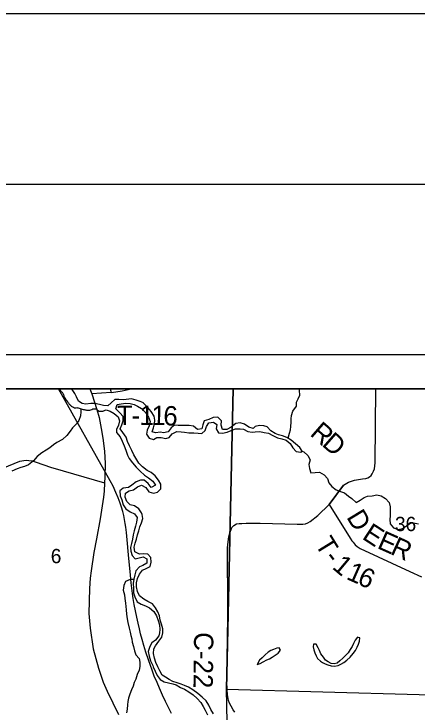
# Model space of a CAD drawing. Extents: x 0 to 34, y 0 to 22.
# Drawn here: x 3.131 to 4.316, y 19.951 to 22 of the extents above; entities that cross this region are included whole.
import ezdxf

# ---------------------------------------------------------------- set-up
doc = ezdxf.new("R2010")
doc.units = 0
for name, color, linetype in [('Default', 7, 'Continuous'), ('GM_X_Corporation', 7, 'Continuous'), ('GM_X_County_Road', 7, 'Continuous'), ('GM_X_County_Road_Text', 7, 'Continuous'), ('GM_X_Interchange_Ramps', 7, 'Continuous'), ('GM_X_Interstate_Route', 7, 'Continuous'), ('GM_X_Major_Lake', 7, 'Continuous'), ('GM_X_Minor_Lake', 7, 'Continuous'), ('GM_X_Minor_River', 7, 'Continuous'), ('GM_X_Section', 7, 'Continuous'), ('GM_X_Township_Road_Text', 7, 'Continuous'), ('GM_X_US_Location', 7, 'Continuous'), ('SH_Border', 7, 'Continuous'), ('SH_Cut_Line', 7, 'Continuous'), ('SH_Data', 7, 'Continuous')]:
    doc.layers.add(name, color=color, linetype=linetype)

msp = doc.modelspace()

# ---------------------------------------------------------------- linework, layer by layer
at = {"layer": 'Default'}
for points in [[(3.7753, 20.9), (2.759, 20.9), (2.7373, 19.9264), (3.7574, 19.9211), (3.7556, 20.0185)], [(4.6239, 20.9), (3.7753, 20.9), (3.7556, 20.0185), (4.6053, 19.9945)]]:
    msp.add_lwpolyline(points, close=True, dxfattribs=at)
at = {"layer": 'GM_X_Corporation'}
for p, q in [((3.4141, 20.9), (3.4158, 20.8932)), ((4.0581, 20.5598), (4.1002, 20.6166))]:
    msp.add_line(p, q, dxfattribs=at)
for points in [[(3.4158, 20.8932), (3.4167, 20.8893), (3.3604, 20.8845)], [(4.1002, 20.6166), (4.1043, 20.6195), (4.1095, 20.6228), (4.1148, 20.6254), (4.1206, 20.6281), (4.132, 20.6311), (4.1561, 20.6354), (4.1654, 20.6364), (4.1718, 20.6385), (4.1765, 20.6414), (4.1811, 20.6457), (4.1844, 20.6506), (4.1879, 20.6576), (4.1908, 20.6646), (4.1925, 20.682), (4.1951, 20.9)], [(3.7801, 19.9505), (3.7759, 19.9571), (3.7694, 19.9679), (3.7648, 19.9768), (3.7621, 19.9844), (3.7606, 19.9905), (3.7584, 20.0025), (3.7574, 20.0156), (3.7573, 20.0422), (3.7594, 20.2318), (3.7596, 20.3052), (3.7592, 20.384), (3.7584, 20.4326), (3.7603, 20.4504), (3.7625, 20.4648), (3.7655, 20.4764), (3.7714, 20.493), (3.7771, 20.4984), (3.7855, 20.5033), (3.7931, 20.5046), (3.8005, 20.5047), (3.8132, 20.505), (3.8548, 20.5052), (3.9639, 20.5027), (3.973, 20.5027), (3.9807, 20.5023), (3.988, 20.5034), (3.9948, 20.506), (4.0019, 20.5104), (4.0241, 20.5275), (4.0581, 20.5598)]]:
    msp.add_lwpolyline(points, dxfattribs=at)
at = {"layer": 'GM_X_County_Road'}
msp.add_lwpolyline([(3.5943, 19.9464), (3.584, 19.9663), (3.5763, 19.9823), (3.5674, 20.0008), (3.5587, 20.021), (3.5518, 20.0372), (3.5437, 20.0566), (3.5373, 20.0738), (3.5322, 20.0878), (3.5262, 20.1046), (3.519, 20.1265), (3.513, 20.1461), (3.5081, 20.1639), (3.5035, 20.1807), (3.5001, 20.1947), (3.4961, 20.2113), (3.4921, 20.2296), (3.4885, 20.2476), (3.4849, 20.2668), (3.4817, 20.284), (3.4796, 20.2991), (3.4775, 20.3141), (3.4755, 20.3304), (3.4733, 20.3522), (3.4677, 20.4128), (3.4638, 20.4563), (3.4618, 20.4781), (3.46, 20.4932), (3.4583, 20.5039), (3.4564, 20.5158), (3.4536, 20.5281), (3.4509, 20.5397), (3.4473, 20.552), (3.4434, 20.5644), (3.4377, 20.5792), (3.431, 20.5955), (3.4223, 20.6138), (3.4135, 20.63), (3.2617, 20.9)], dxfattribs=at)
at = {"layer": 'GM_X_Interchange_Ramps'}
msp.add_lwpolyline([(6.6698, 20.9), (2.1, 20.9), (2.1, 17.9098), (2.4376, 17.9025), (2.6711, 17.8975), (2.9484, 17.8857), (3.604, 17.8577), (3.7063, 17.8588), (3.7128, 17.9822), (4.1825, 17.9744), (4.4481, 17.9728), (4.5919, 17.9719), (4.9267, 17.9702), (4.9368, 17.9702), (4.994, 17.969), (5.3871, 17.9608), (5.6339, 17.9555), (6.0729, 17.9463), (6.24, 17.9427), (6.5943, 17.9356), (6.6079, 18.3189), (6.6258, 18.9603), (6.6304, 19.2166), (6.6438, 19.9593)], close=True, dxfattribs=at)
msp.add_lwpolyline([(3.3543, 20.9), (3.3604, 20.8845), (3.3747, 20.8388), (3.3814, 20.8155), (3.3876, 20.7833), (3.3926, 20.7546), (3.397, 20.7163), (3.3991, 20.6806), (3.3987, 20.6401), (3.3974, 20.624), (3.3964, 20.5991), (3.3941, 20.5816), (3.3843, 20.5177), (3.3737, 20.4598), (3.3662, 20.4188), (3.3585, 20.365), (3.3553, 20.3435), (3.3529, 20.3131), (3.3508, 20.2405), (3.3556, 20.1975), (3.3642, 20.1369), (3.3796, 20.0796), (3.3936, 20.0384), (3.4051, 20.0126), (3.4382, 19.944)], dxfattribs=at)
at = {"layer": 'GM_X_Interstate_Route'}
msp.add_line((4.1002, 20.6166), (4.0581, 20.5598), dxfattribs=at)
for points in [[(3.4167, 20.8893), (3.4309, 20.8907), (3.4489, 20.8938), (3.4761, 20.9)], [(3.0356, 20.6412), (3.1485, 20.6871), (3.1599, 20.6897), (3.1671, 20.6903), (3.1749, 20.6897), (3.1845, 20.6879), (3.1961, 20.6843), (3.2381, 20.6695), (3.2761, 20.6591), (3.3974, 20.624)], [(4.0581, 20.5598), (4.1198, 20.461), (4.1245, 20.4536), (4.1282, 20.4492), (4.134, 20.4419), (4.1396, 20.4373), (4.1491, 20.4311), (4.2946, 20.3639), (4.3294, 20.3474)]]:
    msp.add_lwpolyline(points, dxfattribs=at)
at = {"layer": 'GM_X_Minor_Lake'}
msp.add_lwpolyline([(3.7556, 20.0185), (4.6053, 19.9945), (4.5812, 18.9996), (3.7421, 19.0151), (3.7574, 19.9211)], close=True, dxfattribs=at)
at = {"layer": 'GM_X_Minor_River'}
for points in [[(4.0193, 20.1503), (4.0114, 20.1506), (4.0107, 20.1419), (4.013, 20.1336), (4.0154, 20.1249), (4.0193, 20.1158), (4.0231, 20.1083), (4.0319, 20.1), (4.0377, 20.0966), (4.046, 20.0929), (4.0541, 20.0892), (4.0632, 20.0862), (4.0735, 20.0855), (4.0837, 20.0879), (4.0916, 20.091), (4.1007, 20.0968), (4.1094, 20.1033), (4.1192, 20.1121), (4.1282, 20.1224), (4.135, 20.132), (4.1402, 20.1415), (4.1439, 20.1503), (4.1465, 20.1594), (4.1476, 20.1685), (4.1433, 20.1701)], [(4.1433, 20.1701), (4.1407, 20.1711), (4.1336, 20.1619), (4.1291, 20.152), (4.125, 20.1433), (4.1198, 20.1341), (4.1134, 20.125), (4.1059, 20.1169), (4.0976, 20.1089), (4.0889, 20.1008), (4.081, 20.0947), (4.0726, 20.0924), (4.0639, 20.0934), (4.0551, 20.0983), (4.0471, 20.1035), (4.0406, 20.1122), (4.0329, 20.122), (4.029, 20.1311), (4.0255, 20.1398), (4.0193, 20.1503)], [(3.912, 20.1376), (3.9112, 20.1392), (3.9036, 20.1387), (3.8945, 20.1345), (3.8866, 20.1314), (3.8783, 20.1264), (3.87, 20.1187), (3.8605, 20.1099), (3.853, 20.1034), (3.8463, 20.0908)], [(3.8463, 20.0908), (3.855, 20.0935), (3.8641, 20.0978), (3.8743, 20.104), (3.8818, 20.1074), (3.8901, 20.1124), (3.8985, 20.1178), (3.9075, 20.1236), (3.9147, 20.1328), (3.912, 20.1376)]]:
    msp.add_lwpolyline(points, dxfattribs=at)
at = {"layer": 'GM_X_Township_Road_Text'}
for points in [[(3.937, 20.7548), (3.9406, 20.7692), (3.9443, 20.7791), (3.9453, 20.7886), (3.9464, 20.8015), (3.9459, 20.8114), (3.9473, 20.8216), (3.951, 20.8338), (3.9615, 20.8487), (3.9618, 20.8601), (3.9663, 20.8707), (3.9711, 20.8814), (3.9706, 20.8947), (3.9696, 20.9)], [(3.3279, 20.8414), (3.3281, 20.8318), (3.3267, 20.8208), (3.3215, 20.8067), (3.3147, 20.7968), (3.3031, 20.7853), (3.2967, 20.7758), (3.2869, 20.7628), (3.2734, 20.7513), (3.2575, 20.7421), (3.2477, 20.7348), (3.2367, 20.7263), (3.2262, 20.7198), (3.2133, 20.7113), (3.1994, 20.7006), (3.1881, 20.688), (3.1737, 20.6765), (3.1624, 20.6714), (3.1518, 20.6687), (3.1404, 20.6652), (3.1253, 20.6582)], [(3.4835, 20.3401), (3.4726, 20.3395), (3.4594, 20.3337), (3.4542, 20.3219), (3.4524, 20.3086), (3.4559, 20.2954), (3.4575, 20.2844), (3.4588, 20.2707), (3.4605, 20.251), (3.4621, 20.2385), (3.4638, 20.2241), (3.4661, 20.2135), (3.4693, 20.1972), (3.4725, 20.1855), (3.4748, 20.1753), (3.4772, 20.1654), (3.4788, 20.1556), (3.4823, 20.1431), (3.4859, 20.1302), (3.4894, 20.1185), (3.499, 20.1076), (3.501, 20.097), (3.5007, 20.0844), (3.4989, 20.0734), (3.4937, 20.0612), (3.4889, 20.0475), (3.4848, 20.038), (3.4811, 20.0266), (3.4766, 20.0163), (3.4718, 20.0038), (3.4681, 19.9916), (3.4663, 19.9817), (3.4652, 19.9722), (3.4642, 19.9597), (3.462, 19.9483)]]:
    msp.add_lwpolyline(points, dxfattribs=at)
at = {"layer": 'GM_X_US_Location'}
for points in [[(3.4067, 20.85), (3.3945, 20.8509), (3.3823, 20.8541), (3.369, 20.8565), (3.3568, 20.8567), (3.3424, 20.855), (3.3321, 20.8563), (3.3206, 20.8633), (3.3147, 20.8765), (3.3099, 20.8863), (3.3018, 20.8975), (3.2992, 20.9)], [(3.5119, 20.8582), (3.5023, 20.8622), (3.4901, 20.8661), (3.4771, 20.8705), (3.4528, 20.867), (3.4395, 20.8683), (3.4281, 20.8681), (3.4172, 20.8581), (3.4067, 20.85)], [(3.5063, 20.5356), (3.4981, 20.5476), (3.4858, 20.5558), (3.4728, 20.5594), (3.4628, 20.5687), (3.4584, 20.5815), (3.4593, 20.5936), (3.4702, 20.6003), (3.4823, 20.6028), (3.4947, 20.6124), (3.5064, 20.6164), (3.5191, 20.6098), (3.528, 20.5974), (3.541, 20.5935), (3.5531, 20.5967), (3.5625, 20.6064), (3.563, 20.62), (3.5564, 20.6317), (3.5459, 20.6444), (3.5347, 20.6541), (3.5224, 20.6599), (3.5093, 20.6707), (3.4985, 20.6819), (3.4895, 20.6962), (3.4836, 20.7063), (3.4773, 20.7191), (3.4707, 20.7327), (3.4647, 20.7455), (3.4611, 20.7576), (3.4514, 20.7714), (3.4436, 20.7823), (3.448, 20.7937), (3.4519, 20.806), (3.4521, 20.8189), (3.442, 20.8293), (3.4304, 20.8413), (3.4348, 20.8538), (3.4465, 20.8559), (3.4602, 20.8577), (3.4728, 20.8564), (3.4842, 20.8539), (3.4938, 20.8491), (3.5064, 20.8421), (3.5177, 20.8306), (3.527, 20.8167), (3.5314, 20.8035), (3.5286, 20.7913), (3.5223, 20.7787), (3.5206, 20.7661), (3.5281, 20.7545), (3.541, 20.7509), (3.5512, 20.7564), (3.5641, 20.757), (3.5779, 20.7542), (3.5877, 20.757), (3.5959, 20.7678), (3.6102, 20.7748), (3.6224, 20.7731), (3.6323, 20.7725), (3.6453, 20.7709), (3.6601, 20.77), (3.673, 20.7694), (3.6829, 20.7681), (3.6934, 20.777), (3.6966, 20.7888), (3.7044, 20.8003), (3.7173, 20.8017), (3.7277, 20.7946), (3.7256, 20.7824), (3.7319, 20.7708), (3.7441, 20.7691), (3.7574, 20.7724), (3.7694, 20.7771), (3.7827, 20.7823), (3.7956, 20.7825), (3.8059, 20.7808), (3.8182, 20.7741), (3.8311, 20.7721), (3.8406, 20.7737), (3.8543, 20.774), (3.8669, 20.7711), (3.8798, 20.7698), (3.8925, 20.7628), (3.9059, 20.7562), (3.9181, 20.7527), (3.9315, 20.7487), (3.9434, 20.739), (3.9505, 20.7266), (3.9609, 20.7158), (3.9739, 20.7137), (3.9784, 20.7165)], [(3.8343, 20.7835), (3.8217, 20.7875), (3.809, 20.7964), (3.7957, 20.7999), (3.7832, 20.7978), (3.7693, 20.7873), (3.7565, 20.7803), (3.7439, 20.7801), (3.7403, 20.7926), (3.7416, 20.8059), (3.73, 20.8163), (3.7164, 20.8153), (3.7043, 20.8098), (3.6907, 20.8061), (3.6867, 20.7943), (3.6831, 20.7821), (3.6709, 20.7804), (3.659, 20.7897), (3.646, 20.7921), (3.6236, 20.7917), (3.6137, 20.7923), (3.6031, 20.7925), (3.5933, 20.7852), (3.5848, 20.7737), (3.5711, 20.7708), (3.5616, 20.7725), (3.5476, 20.77), (3.5373, 20.7732), (3.5409, 20.7851), (3.5445, 20.7965), (3.5454, 20.8079), (3.5429, 20.8196), (3.5347, 20.8328), (3.5246, 20.8451), (3.5111, 20.8582), (3.5119, 20.8582)], [(3.4021, 20.8376), (3.4138, 20.8341), (3.4253, 20.8275), (3.4373, 20.8178), (3.4413, 20.8058), (3.4381, 20.7932), (3.4322, 20.7806), (3.4328, 20.7711), (3.4429, 20.7584), (3.4495, 20.746), (3.4547, 20.732), (3.4599, 20.7192), (3.4647, 20.7049), (3.4698, 20.6951), (3.4791, 20.682), (3.4903, 20.6693), (3.5023, 20.6581), (3.5147, 20.6458), (3.527, 20.638), (3.5397, 20.6287), (3.5467, 20.6167), (3.5343, 20.6105), (3.5257, 20.6217), (3.5134, 20.6313), (3.5035, 20.6319), (3.4899, 20.6264), (3.4775, 20.6171), (3.4674, 20.6097), (3.4526, 20.6079), (3.4428, 20.6002), (3.4438, 20.5858), (3.4486, 20.5734), (3.4526, 20.5594), (3.4601, 20.5478), (3.4724, 20.5381), (3.4854, 20.5326), (3.4936, 20.5218), (3.4915, 20.5081), (3.4887, 20.4963), (3.4847, 20.4833), (3.4815, 20.4711), (3.4794, 20.4582), (3.477, 20.446), (3.4741, 20.4338), (3.4747, 20.4232), (3.4787, 20.41), (3.4876, 20.4003), (3.4993, 20.4039), (3.5111, 20.4064), (3.5218, 20.4008), (3.522, 20.3883), (3.5104, 20.3809), (3.4998, 20.3773), (3.4897, 20.3658), (3.4869, 20.354), (3.4837, 20.3414), (3.482, 20.3281), (3.4826, 20.3145), (3.4828, 20.3008), (3.4861, 20.2887), (3.4931, 20.2748), (3.5051, 20.2674), (3.5181, 20.2631), (3.5299, 20.2572), (3.5419, 20.2464), (3.5505, 20.2336), (3.5553, 20.2201), (3.5589, 20.2072), (3.5599, 20.1936), (3.5585, 20.1837), (3.5568, 20.1742), (3.5471, 20.1619), (3.5362, 20.1537), (3.5303, 20.143), (3.526, 20.1282), (3.5289, 20.1149), (3.5329, 20.1017), (3.5389, 20.0874)], [(3.9784, 20.7165), (3.971, 20.7274), (3.9583, 20.7378), (3.9459, 20.7493), (3.9332, 20.7571), (3.9202, 20.7614), (3.9088, 20.765), (3.8992, 20.7683), (3.8862, 20.7764), (3.8753, 20.7884), (3.8658, 20.7912), (3.8532, 20.7918), (3.8399, 20.7893), (3.8343, 20.7835)], [(3.9784, 20.7165), (3.983, 20.7143), (3.9946, 20.7038), (4.002, 20.6911), (3.9981, 20.6774), (4.0001, 20.666), (4.0042, 20.6532), (4.0167, 20.6541), (4.0296, 20.6547), (4.0427, 20.6474), (4.0527, 20.6365), (4.0571, 20.6241), (4.0657, 20.6125), (4.0787, 20.6036), (4.091, 20.5985), (4.1032, 20.5941), (4.1144, 20.5848), (4.124, 20.5774), (4.1368, 20.5662), (4.1492, 20.5729), (4.1609, 20.5803), (4.1707, 20.5846), (4.184, 20.5856), (4.198, 20.5881), (4.2106, 20.5857), (4.2232, 20.5775), (4.2345, 20.5663), (4.237, 20.5535), (4.2372, 20.5398), (4.2366, 20.5273), (4.2357, 20.5163), (4.2374, 20.503), (4.2467, 20.4914), (4.2601, 20.4863), (4.2734, 20.4896), (4.2854, 20.4977), (4.2982, 20.5063), (4.3104, 20.505), (4.3199, 20.5032)], [(3.7172, 19.9458), (3.7094, 19.9582), (3.7039, 19.9706), (3.6964, 19.9834), (3.6848, 19.995), (3.6714, 20.0054), (3.6571, 20.0165), (3.6445, 20.0239), (3.6322, 20.029), (3.6226, 20.0323), (3.6104, 20.0362), (3.5978, 20.0406), (3.5878, 20.0465), (3.5763, 20.0535), (3.5667, 20.059), (3.5596, 20.0718), (3.5545, 20.0839), (3.5482, 20.0959), (3.5442, 20.1095), (3.5413, 20.1231), (3.5418, 20.136), (3.5474, 20.1456), (3.5567, 20.1586), (3.566, 20.1705), (3.5684, 20.1831), (3.5686, 20.1953), (3.565, 20.2085), (3.5613, 20.2205), (3.5585, 20.233), (3.5545, 20.2451), (3.5474, 20.2571), (3.5381, 20.2683), (3.5251, 20.2749), (3.5128, 20.282), (3.4997, 20.2916), (3.4942, 20.3048), (3.4917, 20.318), (3.4911, 20.3302), (3.4947, 20.3431), (3.4998, 20.3553), (3.5087, 20.3669), (3.52, 20.3724), (3.5317, 20.3782), (3.5345, 20.3908), (3.5336, 20.4045), (3.5246, 20.4142), (3.5121, 20.4155), (3.4999, 20.4145), (3.4865, 20.4215), (3.4848, 20.4344), (3.4872, 20.4465), (3.4916, 20.458), (3.4944, 20.4706), (3.498, 20.4824), (3.5016, 20.4946), (3.5064, 20.5064), (3.5096, 20.5194), (3.5075, 20.5307), (3.5063, 20.5356)], [(3.5389, 20.0874), (3.5401, 20.0832), (3.5519, 20.0584), (3.5612, 20.046), (3.5731, 20.0394), (3.5849, 20.0369), (3.5979, 20.0341), (3.6075, 20.0312), (3.6205, 20.0231), (3.6324, 20.018), (3.6447, 20.0106), (3.6578, 20.0014), (3.6701, 19.9909), (3.6805, 19.9794), (3.6868, 19.9673), (3.6931, 19.956), (3.7005, 19.9429)]]:
    msp.add_lwpolyline(points, dxfattribs=at)
msp.add_open_spline([(3.2646, 20.9), (3.2656, 20.8983), (3.2666, 20.8967), (3.2676, 20.8951), (3.2697, 20.8919), (3.273, 20.8897), (3.275, 20.8866), (3.2769, 20.8835), (3.2772, 20.8797), (3.2789, 20.8765), (3.2817, 20.8713), (3.2848, 20.8665), (3.2886, 20.8617), (3.2938, 20.855), (3.2992, 20.8485), (3.3072, 20.8451), (3.3112, 20.8433), (3.3158, 20.8449), (3.32, 20.8439), (3.3258, 20.8424), (3.3314, 20.8397), (3.3374, 20.8385), (3.3421, 20.8375), (3.347, 20.8373), (3.3517, 20.8373), (3.3575, 20.8373), (3.3632, 20.8413), (3.3688, 20.8412), (3.3739, 20.841), (3.378, 20.8346), (3.3831, 20.8342), (3.3867, 20.8339), (3.3908, 20.8337), (3.3944, 20.835), (3.397, 20.8358), (3.3995, 20.8367), (3.4021, 20.8376)], degree=3, dxfattribs=at)
at = {"layer": 'SH_Border'}
msp.add_lwpolyline([(1.5, 21.5), (33.5, 21.5), (33.5, 0.5), (1.5, 0.5)], close=True, dxfattribs=at)
at = {"layer": 'SH_Cut_Line'}
for points in [[(0, 0), (34, 0), (34, 22), (0, 22)], [(8.9, 17.8921), (8.9, 20.9), (2.1, 20.9), (2.1, 17.9098), (2.4376, 17.9025), (2.6711, 17.8975), (2.9484, 17.8857), (3.604, 17.8577), (3.7063, 17.8588), (3.7128, 17.9822), (4.1825, 17.9744), (4.4481, 17.9728), (4.5919, 17.9719), (4.9267, 17.9702), (4.9368, 17.9702), (4.994, 17.969), (5.3871, 17.9608), (5.6339, 17.9555), (6.0729, 17.9463), (6.24, 17.9427), (6.5943, 17.9356), (7.6027, 17.9156), (8.3297, 17.9059), (8.5492, 17.9006)]]:
    msp.add_lwpolyline(points, close=True, dxfattribs=at)
at = {"layer": 'SH_Data'}
for p, q in [((2, 21), (9, 21)), ((2.1, 20.9), (8.9, 20.9))]:
    msp.add_line(p, q, dxfattribs=at)

# ---------------------------------------------------------------- texts
at = {"layer": 'GM_X_County_Road_Text'}
for s, height, p in [('36', 0.04186, (4.2511, 20.482)), ('6', 0.0419, (3.2394, 20.3878))]:
    msp.add_text(s, height=height, rotation=0, dxfattribs=at).set_placement(p)
at = {"layer": 'GM_X_Major_Lake'}
msp.add_text('C-22', height=0.05682, rotation=269.3129, dxfattribs=at).set_placement((3.6607, 20.1856))
at = {"layer": 'GM_X_Section'}
for s, rotation, p in [('T', 0.3857, (3.4342, 20.7933)), ('1', 359.7684, (3.4999, 20.7937)), ('1', 359.0711, (3.5347, 20.7936)), ('6', 357.8972, (3.5694, 20.793)), ('-', 0.2342, (3.4767, 20.7936)), ('R', 319.005, (3.9986, 20.7649)), ('D', 318.6989, (4.0337, 20.7344)), ('D', 301.2686, (4.1071, 20.5232)), ('E', 326.7438, (4.1517, 20.4611)), ('T', 301.537, (4.0144, 20.4439)), ('E', 336.0812, (4.196, 20.433)), ('R', 335.3886, (4.2346, 20.4159)), ('-', 307.2158, (4.0401, 20.4026)), ('1', 320.0157, (4.0637, 20.374)), ('1', 336.1542, (4.1053, 20.3423)), ('6', 335.2645, (4.1371, 20.3283))]:
    msp.add_text(s, height=0.0568, rotation=rotation, dxfattribs=at).set_placement(p)

doc.saveas('drawing.dxf')
